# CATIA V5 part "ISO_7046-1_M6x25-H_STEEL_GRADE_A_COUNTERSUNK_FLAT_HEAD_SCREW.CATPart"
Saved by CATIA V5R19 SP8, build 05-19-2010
Part number: ISO 7046-1 SCREW M6x25-H STEEL GRADE A COUNTERSUNK FLAT HEAD
Nomenclature: 30
Publications: "Axis", "Mating Edge"
Bounding box of the stored display mesh (mm): x -25 to 0, y -5.648 to 5.648, z -5.647 to 5.647
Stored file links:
  C:\Users\rphgr\Desktop\0_Tapis_TC520B_vitesse\ISO_7046-1_M6x25-H_STEEL_GRADE_A_COUNTERSUNK_FLAT_HEAD_SCREW.CATPart
  D:\Programmes\DassaultSysteme\win_b64\startup\components\MechanicalStandardParts\EN_Standards\Design_Tables\EN_ISO_7046_1_COUNTERSUNK_FLAT_HEAD_SCREW_CLASS_4.txt
  C:\Program Files\Dassault Systemes\B19\win_b64\startup\components\MechanicalStandardParts\ISO_Standards\Design_Tables\ISO_7046_1_COUNTERSUNK_FLAT_HEAD_SCREW.txt
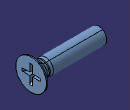
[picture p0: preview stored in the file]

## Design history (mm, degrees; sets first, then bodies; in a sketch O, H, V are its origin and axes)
Parameters
  d_dia = 6 mm
  Threading = 19.7 mm
  l_nom = 25 mm
  dk_nom = 11.3 mm
  k_max = 3.3 mm
  r_max = 1.5 mm
  m_ref = 6.8 mm
  m_penetration_max = 3.5 mm
  P_pitch = 1 mm
  Slot_width = 1.03 mm
  type = "H"
Body1 "PartBody" (main body)
  Sketch1 on zx-plane, origin (0, 0, 0), H (-1, 0, 0), V (0, 0, 1)
    line L1 (0, 0) -> (0, 5.65)
    line L2 (0, 5.65) -> (0.4, 5.65)
    point P2 (0.4, 5.65)
    line L3 (0.4, 5.65) -> (3.3, 2.75)
    line L4 (3.3, 2.75) -> (4.3, 2.75)
    point P3 (4.3, 2.75)
    line L5 (4.3, 2.75) -> (5.3, 2.9268)
    point P4 (5.3, 2.9268)
    line L6 (5.3, 2.9268) -> (25, 2.9268)
    line L7 (25, 2.9268) -> (25, 0)
    point P6 (25, 0)
    axis line L8 (-61.1381, 0) -> (162.5378, 0)
    point P9 (3.3, 2.75)
    distance P2 L1 = 0.4 {= P_pitch /2.5}
    angle L8 L3 = 45
    distance P3 P4 H = 1 {= P_pitch}
    distance P4 L7 = 19.7 {= Threading}
    distance L1 L7 = 25 {= l_nom}
    distance L6 L8 = 2.9268 {= d_dia /2.05}
    length L1 = 5.65 {= dk_nom /2}
    distance P9 L1 = 3.3 {= k_max}
    vertical: L1 V, L7 V
    horizontal: L2 H, L4 H, L6 H, L8 H
    fix: L8
    coincidence: P6 L8
  Shaft1: profile Sketch1, axis Sketch1.L8, angle 360
  Fillet1: radius 1.5 {= r_max}, on edge [face of Shaft1 | face of Shaft1]
  Body2
    Sketch2 on zx-plane, origin (0, 0, 0), H (-1, 0, 0), V (0, 0, 1)
      point P1 (3.5, 0)
      line L1 (0, 3.4) -> (0, -3.4)
      point P2 (0, 3.4)
      point P3 (0, -3.4)
      reference intersected line E1 through (1000000, 0) direction (-1, 0) from xy-plane
      reference projected line E2 (0, 9.15) -> (0, 8.0299) from edge [face of Shaft1 | face of Shaft1]
      line L2 (0, 3.4) -> (3.5, 0.515)
      point P4 (3.5, 0.515)
      line L3 (3.5, 0.515) -> (3.5, -0.515)
      point P5 (3.5, -0.515)
      line L4 (3.5, -0.515) -> (0, -3.4)
      distance O P1 = 3.5 {= m_penetration_max}
      distance P2 E1 = 3.4 {= m_ref /2}
      distance O P3 = 3.4 {= m_ref /2}
      distance P4 H = 0.515 {= Slot_width /2}
      distance P5 H = 0.515 {= Slot_width /2}
      vertical: L1 V, L3 V
      coincidence: L1 E2, L3 P1
    Pad1: profile Sketch2, direction (0, 1, 0), length 0.515 {= Slot_width /2}, mirrored extent
    CircPattern1: of Pad1, instances 2, angular step 90, axis from face of Shaft1
  Remove1: tool Body2
  Thread1: diameter 5.8537 {= d_dia /1.025}, depth 19.7 {= Threading}, pitch 1, on face of Shaft1, from face of Shaft1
